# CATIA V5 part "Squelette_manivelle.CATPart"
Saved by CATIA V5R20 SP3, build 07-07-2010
Part number: Squelette_manivelle
Publications: "Point.1", "Droite.1", "Droite.2", "Plan.1", "Plan.2", "Plan.3", "Droite.3", "Point.3", "Plan.4", "Plan.5"
Bounding box of the stored display mesh (mm): x -10 to 10, y 0 to 50, z 0 to 2
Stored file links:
  C:\Documents and Settings\Propriétaire\Mes documents\IFMA\COURS\PROJ IAO\CATIA\Squelette_manivelle.CATPart
  C:\Documents and Settings\Propriétaire\Mes documents\IFMA\COURS\PROJ IAO\CATIA\Assemblage Squelette.CATProduct
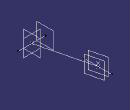
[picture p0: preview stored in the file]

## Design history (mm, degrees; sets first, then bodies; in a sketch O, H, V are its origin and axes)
Set1
  Point1: linked copy from another document
Set2
  Plane1: type Offset, RefPlane yz-plane, Offset 0
  Point2: type OnPlane, Support Plane2, H 40, V 0, Direction (0, 1, 0)
  Line1: type PtPt, FirstPoint Point2, SecondPoint Point1
  Line2: type PtDir, RefPoint Point1, Direction Plane1, Start -10, End 10
  Plane2: type Offset, RefPlane Plane1, Offset 10, reversed
  Plane3: type Offset, RefPlane zx-plane, Offset 0
  Line3: type PtDir, RefPoint Point2, Direction Plane3, Start -10, End 10
  Point3: type OnPlane, Support Plane2, H 40, V 2, Direction (0, 1, 0)
  Plane4: type 1Line1Pt, RefPoint Point3, Line Line1
  Plane5: type Offset, RefPlane Plane4, Offset 4, reversed
Body1 (main body)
